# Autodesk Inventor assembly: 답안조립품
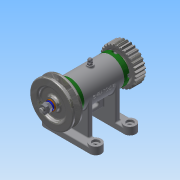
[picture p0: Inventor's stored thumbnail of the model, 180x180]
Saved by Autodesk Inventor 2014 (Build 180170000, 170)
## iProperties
Created: 2015-11
Part Number: 답안조립품
Document SubType Name: Assembly
Designer: 103-06
Author: 103-06
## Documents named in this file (16)
- C:\Users\103-06\Desktop\451110V1028\답안조립품.iam
- C:\Users\103-06\Desktop\451110V1028\1-본체.ipt
- C:\Users\103-06\Desktop\451110V1028\베어링 15 x 32 x 9.ipt
- C:\Users\103-06\Desktop\451110V1028\축.ipt
- C:\Users\103-06\Desktop\451110V1028\키 3 x 3 x 12.ipt
- C:\Users\103-06\Desktop\451110V1028\V벨트풀리.ipt
- C:\Users\103-06\Desktop\451110V1028\너트 M 8.ipt
- C:\Users\103-06\Desktop\451110V1028\스프링와셔 8.ipt
- C:\Users\103-06\Desktop\451110V1028\와셔 8x17.ipt
- C:\Users\103-06\Desktop\451110V1028\커버.ipt
- C:\Users\103-06\Desktop\451110V1028\오일 실 15 25 7.ipt
- C:\Users\103-06\Desktop\451110V1028\볼트 M4 x 12.ipt
- C:\Users\103-06\Desktop\451110V1028\스퍼기어.ipt
- C:\Users\103-06\Desktop\451110V1028\니플 M 6 x 0.75.ipt
- C:\Users\103-06\Desktop\451110V1028\볼트 M 6 x 8.ipt
- C:\Users\103-06\Desktop\451110V1028\와셔 6x11.5.ipt
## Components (12 placed, 4 different names)
1. 1-본체:1
2. KS B 2023 6002 - 15 x 32 x 9:1
3. KS B 2023 6002 - 15 x 32 x 9:2
4. V벨트풀리:1
5. ISO 4762 M4 x 12:1
6. ISO 4762 M4 x 12:3
7. ISO 4762 M4 x 12:4
8. ISO 4762 M4 x 12:5
9. ISO 4762 M4 x 12:2
10. ISO 4762 M4 x 12:6
11. ISO 4762 M4 x 12:7
12. ISO 4762 M4 x 12:8
## Named parameters: d39_d18 = 0, d40_d20 = 0, d41_d22 = 0
